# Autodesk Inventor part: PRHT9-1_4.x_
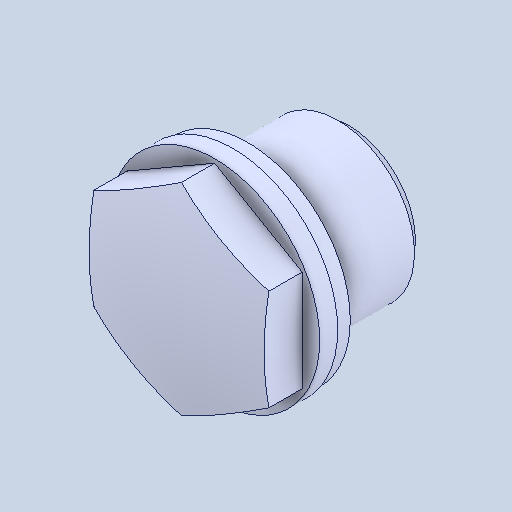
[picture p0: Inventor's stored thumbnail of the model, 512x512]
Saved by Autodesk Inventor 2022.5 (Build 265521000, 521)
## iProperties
Created: 2024-09
Part Number: PRHT9-1_4.x_
Material: 一般
Document SubType Name: Modeling
Designer: ImaoCorp
Density: 1 g/cm^3
Appearance: 既定
Author: ImaoCorp
Sending System: SOLIDWORKS 2022-2022290
MC: AMD64
MC_MODEL: Intel64 Family 6 Model 60 Stepping 3, GenuineIntel
OS: Windows_NT
FRU: Parasolid Version 33.1, build 260,  4-25-2022
FORMAT: text
GUISE: transmit
KEY: FILEPRHT9-1_4.x_t
DATE: Tue Sep  3 15:13:47 2024
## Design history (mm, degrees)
feature "Base1"
node "ソリッド1"
